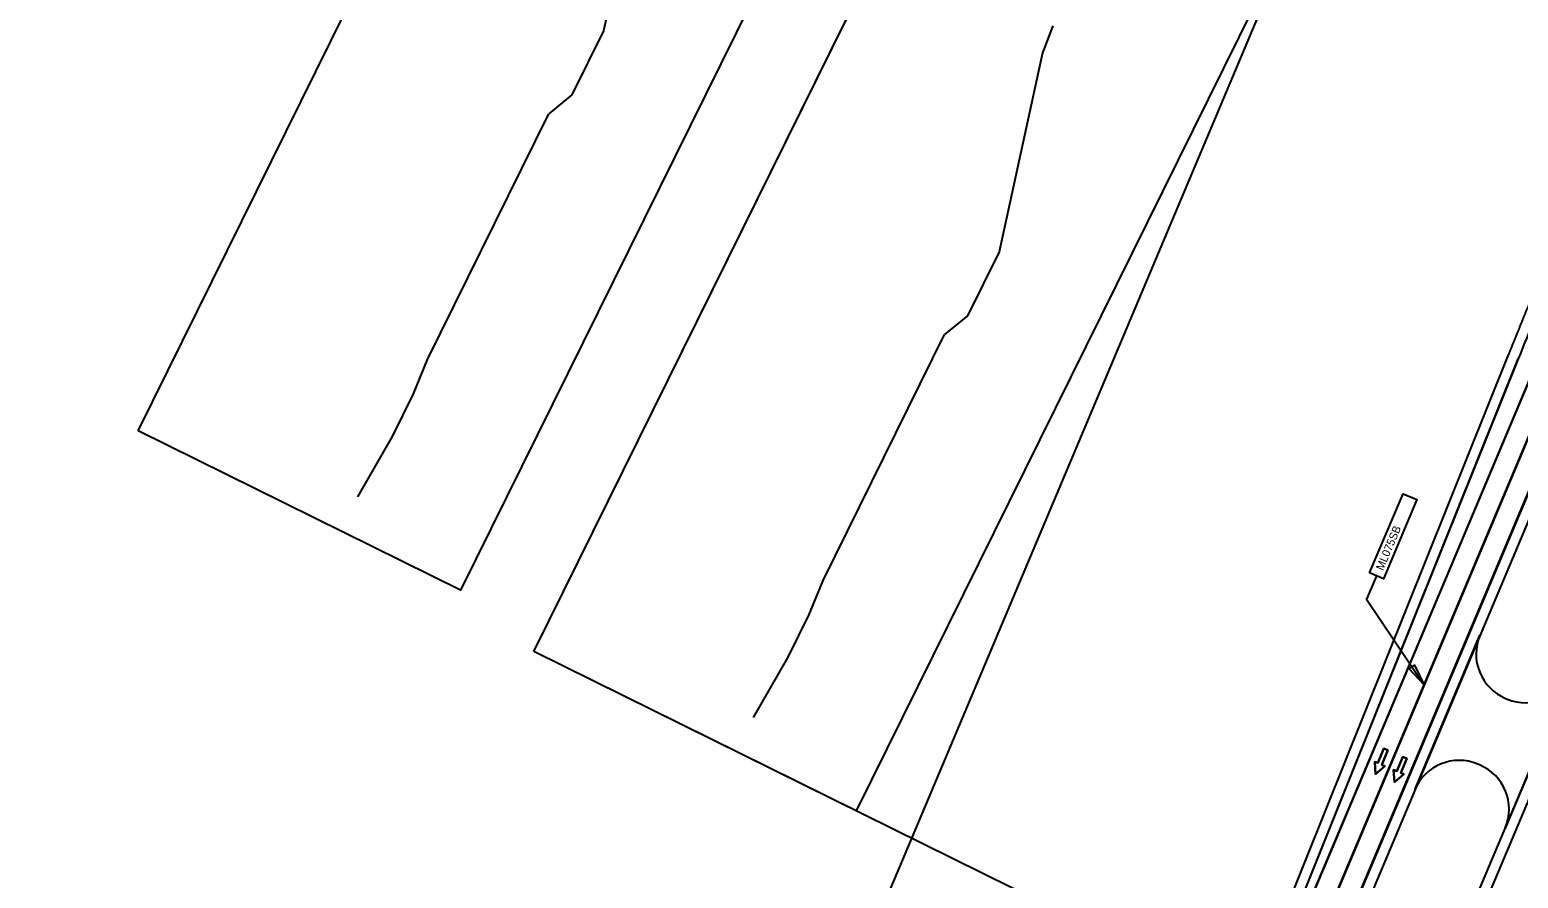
# Model space of a CAD drawing. Extents: x 14104283 to 14129344, y 8637090 to 8673339.
# Drawn here: x 14117810 to 14118644, y 8667727 to 8668202 of the extents above; entities that cross this region are included whole.
import ezdxf

# ---------------------------------------------------------------- set-up
doc = ezdxf.new("R2010")
doc.units = 0
for name, color, linetype in [('dsnNonPlotable', 7, 'Continuous'), ('dsnPaintExistingBrokenLaneLineWhite', 7, 'Continuous'), ('dsnPaintExistingEdgeLineLeftYellow', 7, 'Continuous'), ('dsnPaintExistingEdgeLineRightWhite', 7, 'Continuous'), ('dsnShadingPaved', 7, 'Continuous'), ('dsnStgShadingPrevPav', 7, 'Continuous'), ('dsnTextFinalPlan', 7, 'Continuous'), ('dsnTextOverlapEven', 7, 'Continuous'), ('Level 2', 7, 'Continuous'), ('Level 5', 7, 'Continuous'), ('Terrain', 7, 'Continuous'), ('Text', 7, 'Continuous')]:
    doc.layers.add(name, color=color, linetype=linetype)

msp = doc.modelspace()

# ---------------------------------------------------------------- linework, layer by layer
at = {"layer": 'dsnNonPlotable'}
for points in [[(14118092.03, 8667853.71), (14118786.76, 8669258.84), (14119692.14, 8668811.2), (14118997.41, 8667406.07)], [(14118056.48, 8667161.91), (14118665.06, 8668606.45), (14119130.44, 8668410.38), (14118521.87, 8666965.84)]]:
    msp.add_lwpolyline(points, close=True, dxfattribs=at)
at = {"layer": 'dsnPaintExistingBrokenLaneLineWhite'}
msp.add_line((14118664.08, 8668008.96), (14118424.31, 8667439.59), dxfattribs=at)
at = {"layer": 'dsnPaintExistingEdgeLineLeftYellow'}
for p, q in [((14115900.95, 8661243.95), (14118759.37, 8668031.7)), ((14118675.14, 8668004.3), (14118435.37, 8667434.94))]:
    msp.add_line(p, q, dxfattribs=at)
at = {"layer": 'dsnPaintExistingEdgeLineRightWhite'}
msp.add_line((14118643.53, 8668017.62), (14118412.94, 8667444.38), dxfattribs=at)
msp.add_arc((14123767.91, 8665959.11), 5522.39, 157.04925, 158.11426, dxfattribs=at)
at = {"layer": 'dsnShadingPaved'}
for p, q in [((14118227.72, 8666769.23), (14118759.37, 8668031.7)), ((14118528.39, 8667730.93), (14118643.53, 8668017.62)), ((14118646.49, 8667998.13), (14118579.27, 8667838.49)), ((14118576.7, 8667832.39), (14118534.18, 8667731.73)), ((14118534.18, 8667731.73), (14118412.93, 8667443.47)), ((14118412.93, 8667443.47), (14118528.39, 8667730.93))]:
    msp.add_line(p, q, dxfattribs=at)
for points in [[(14118653.02, 8668013.62), (14118412.94, 8667444.38), (14118424.31, 8667439.59), (14118664.08, 8668008.96)], [(14118435.37, 8667434.94), (14118675.14, 8668004.3), (14118664.08, 8668008.96), (14118424.15, 8667439.66)]]:
    msp.add_lwpolyline(points, close=True, dxfattribs=at)
at = {"layer": 'dsnStgShadingPrevPav'}
for p, q in [((14115895.65, 8661246.83), (14118811.53, 8668171.01)), ((14118457.98, 8667555.62), (14118643.53, 8668017.62)), ((14118457.98, 8667555.62), (14118643.53, 8668017.62)), ((14118637.96, 8668019.85), (14118497.16, 8667669.27)), ((14118653.02, 8668013.62), (14115794.02, 8661224.52)), ((14118652.65, 8668013.06), (14118415.89, 8667450.85)), ((14115816.14, 8661215.2), (14118675.14, 8668004.3)), ((14115816.14, 8661215.2), (14118675.14, 8668004.3)), ((14118680.66, 8668001.98), (14115821.67, 8661212.88)), ((14118585.57, 8667776.15), (14118622.05, 8667862.79)), ((14118672.74, 8667841.44), (14118636.26, 8667754.81)), ((14118636.45, 8667827.42), (14118637.38, 8667827.04)), ((14118621.85, 8667790.17), (14118620.93, 8667790.56))]:
    msp.add_line(p, q, dxfattribs=at)
for centre, start, end in [((14118646.93, 8667852.31), 157.1633, 247.1633), ((14118647.86, 8667851.92), 247.1633, 337.1633), ((14118610.45, 8667765.68), 67.1633, 157.1633), ((14118611.37, 8667765.29), 337.1633, 67.1633)]:
    msp.add_arc(centre, 27, start, end, dxfattribs=at)
msp.add_open_spline([(14118677.15, 8668114.84), (14118676.77, 8668113.95), (14118675.45, 8668110.85), (14118673.07, 8668105.18), (14118671.18, 8668100.7), (14118669.16, 8668095.89), (14118667.19, 8668091.17), (14118665.21, 8668086.42), (14118663.23, 8668081.68), (14118661.26, 8668076.94), (14118659.29, 8668072.19), (14118657.33, 8668067.44), (14118655.38, 8668062.69), (14118653.42, 8668057.94), (14118651.47, 8668053.18), (14118649.53, 8668048.43), (14118647.59, 8668043.66), (14118645.66, 8668038.92), (14118643.7, 8668034.09), (14118641.88, 8668029.58), (14118639.58, 8668023.88), (14118638.32, 8668020.76), (14118637.96, 8668019.85)], degree=2, dxfattribs=at)
at = {"layer": 'dsnTextFinalPlan'}
for points in [[(14117870.36, 8667977.42), (14118384.92, 8669018.16), (14118565.56, 8668928.85), (14118050.99, 8667888.12)], [(14118092.03, 8667853.71), (14118606.59, 8668894.44), (14118787.23, 8668805.14), (14118272.66, 8667764.4)]]:
    msp.add_lwpolyline(points, close=True, dxfattribs=at)
at = {"layer": 'dsnTextOverlapEven'}
msp.add_lwpolyline([(14117870.36, 8667977.42), (14118384.92, 8669018.16), (14118565.56, 8668928.85), (14118050.99, 8667888.12)], close=True, dxfattribs=at)
at = {"layer": 'Level 2'}
for points in [[(14118570.55, 8667798.33), (14118568.24, 8667799.3), (14118564.85, 8667791.24), (14118563.12, 8667791.96), (14118563.57, 8667784.99), (14118568.88, 8667789.54), (14118567.15, 8667790.26)], [(14118581.16, 8667793.77), (14118578.85, 8667794.74), (14118575.46, 8667786.68), (14118573.73, 8667787.41), (14118574.19, 8667780.43), (14118579.49, 8667784.98), (14118577.76, 8667785.71)]]:
    msp.add_lwpolyline(points, close=True, dxfattribs=at)
at = {"layer": 'Level 5'}
for points in [[(14118567.15, 8667790.26), (14118568.88, 8667789.54), (14118563.57, 8667784.99), (14118563.12, 8667791.96), (14118564.85, 8667791.24), (14118568.24, 8667799.3), (14118570.55, 8667798.33), (14118567.15, 8667790.26)], [(14118577.76, 8667785.71), (14118579.49, 8667784.98), (14118574.19, 8667780.43), (14118573.73, 8667787.41), (14118575.46, 8667786.68), (14118578.85, 8667794.74), (14118581.16, 8667793.77), (14118577.76, 8667785.71)]]:
    msp.add_lwpolyline(points, dxfattribs=at)
at = {"layer": 'Terrain'}
for p, q in [((14118155.41, 8668312.82), (14118131.11, 8668201.36)), ((14118131.11, 8668201.36), (14118113.38, 8668165.5)), ((14118382.75, 8668204.17), (14118377.08, 8668189.1)), ((14118377.08, 8668189.1), (14118352.78, 8668077.64)), ((14118113.38, 8668165.5), (14118100.54, 8668154.92)), ((14118032.46, 8668017.23), (14118100.54, 8668154.92)), ((14118352.78, 8668077.64), (14118335.05, 8668041.78)), ((14118335.05, 8668041.78), (14118322.21, 8668031.21)), ((14118254.13, 8667893.51), (14118322.21, 8668031.21))]:
    msp.add_line(p, q, dxfattribs=at)
for points in [[(14117993.44, 8667940.37), (14118012.83, 8667974.21), (14118024.64, 8667998.1), (14118032.46, 8668017.23)], [(14118215.11, 8667816.65), (14118234.5, 8667850.5), (14118246.3, 8667874.39), (14118254.13, 8667893.51)]]:
    msp.add_lwpolyline(points, dxfattribs=at)
at = {"layer": 'Text'}
for points in [[(14118560.3, 8667897.76), (14118578.98, 8667942.1), (14118586.72, 8667938.84), (14118568.04, 8667894.5)], [(14118560.3, 8667897.76), (14118578.98, 8667942.1), (14118586.72, 8667938.84), (14118568.04, 8667894.5)], [(14118590.56, 8667835.2), (14118582.51, 8667844.03), (14118585.46, 8667846)]]:
    msp.add_lwpolyline(points, close=True, dxfattribs=at)
msp.add_lwpolyline([(14118564.17, 8667896.13), (14118558.54, 8667882.99), (14118590.56, 8667835.2)], dxfattribs=at)

# ---------------------------------------------------------------- texts
msp.add_text('ML075SB', height=4.484, rotation=67.1547, dxfattribs=at).set_placement((14118567.77, 8667898.73))

doc.saveas('drawing.dxf')
